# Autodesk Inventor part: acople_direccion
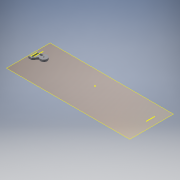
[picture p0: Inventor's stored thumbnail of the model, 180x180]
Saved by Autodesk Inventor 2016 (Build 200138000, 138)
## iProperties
Created: 2017-06
Part Number: acople_direccion
Material: Generic
Document SubType Name: Modeling
Designer: laboratorioesan
Density: 1 g/cm^3
Appearance: Default
Author: laboratorioesan
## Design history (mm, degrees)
workplane "Work Plane1"
sketch "Sketch1"
  geometry: L1 (-120, 104.183)-(-120, 85.683) reference; L2 (-120, 85.683)-(-180, 85.683) reference; L3 (-180, 85.683)-(-180, 104.183) reference; L4 (-180, 104.183)-(-120, 104.183) reference; L5 (370, 85.683)-(370, 104.183) reference; L6 (370, 104.183)-(430, 104.183) reference; L7 (430, 104.183)-(430, 85.683) reference; L8 (430, 85.683)-(370, 85.683) reference; L9 (180, 104.183)-(180, 85.683) reference; L10 (180, 85.683)-(120, 85.683) reference; L11 (120, 85.683)-(120, 104.183) reference; L12 (120, 104.183)-(180, 104.183) reference; L13 (-370, 104.183)-(-370, 85.683) reference; L14 (-370, 85.683)-(-430, 85.683) reference; L15 (-430, 85.683)-(-430, 104.183) reference; L16 (-430, 104.183)-(-370, 104.183) reference; L17 (448.5, -177.817)-(448.5, -117.817) reference; L18 (448.5, -117.817)-(467, -117.817) reference; L19 (467, -117.817)-(467, -177.817) reference; L20 (467, -177.817)-(448.5, -177.817) reference; L21 (-467, -177.817)-(-467, -117.817) reference; L22 (-467, -117.817)-(-448.5, -117.817) reference; L23 (-448.5, -117.817)-(-448.5, -177.817) reference; L24 (-448.5, -177.817)-(-467, -177.817) reference; L25 (400, 37.183)-(400, 55.683) reference; L26 (400, 55.683)-(460, 55.683) reference; L27 (460, 55.683)-(460, 37.183) reference; L28 (460, 37.183)-(400, 37.183) reference; L29 (190, 37.183)-(190, 55.683) reference; L30 (190, 55.683)-(250, 55.683) reference; L31 (250, 55.683)-(250, 37.183) reference; L32 (250, 37.183)-(190, 37.183) reference; L33 (-30, 37.183)-(-30, 55.683) reference; L34 (-30, 55.683)-(30, 55.683) reference; L35 (30, 55.683)-(30, 37.183) reference; L36 (30, 37.183)-(-30, 37.183) reference; L37 (-460, 37.183)-(-460, 55.683) reference; L38 (-460, 55.683)-(-400, 55.683) reference; L39 (-400, 55.683)-(-400, 37.183) reference; L40 (-400, 37.183)-(-460, 37.183) reference; L41 (-250, 37.183)-(-250, 55.683) reference; L42 (-250, 55.683)-(-190, 55.683) reference; L43 (-190, 55.683)-(-190, 37.183) reference; L44 (-190, 37.183)-(-250, 37.183) reference; L45 (-477.824, 115.072)-(-530, 37.183) reference; L46 (-530, 37.183)-(-530, -47.503) reference; L47 (-530, -47.503)-(-485.998, -191.117) reference; L48 (-428.63, -233.54)-(-370, -233.54) reference; L49 (-370, -233.54)-(-370, -52.817) reference; L50 (-310, 7.183)-(310, 7.183) reference; L51 (370, -52.817)-(370, -233.54) reference; L52 (370, -233.54)-(428.63, -233.54) reference; L53 (485.998, -191.117)-(530, -47.503) reference; L54 (530, -47.503)-(530, 37.183) reference; L55 (530, 37.183)-(477.824, 115.072) reference; L56 (427.975, 141.679)-(-427.975, 141.679) reference; L57 (-470, 37.183)-(-495, 55.683) reference; L58 (-460, 37.183)-(-470, 37.183) reference; L59 (-448.5, -92.817)-(-467, -92.817) reference; L60 (-505.617, 17.183)-(-560, 17.183); L61 (-560, 17.183)-(-560, -22.817); L62 (-558.781, 46.433)-(-560, 46.433); L63 (-560, 17.183)-(-560, -67.817); L64 (-560, -67.817)-(-530, -67.817)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; C1 r 5.25 at (-480, -2.817) reference; C2 r 5.25 at (480, -2.817) reference; A1 r 60 centre (-427.975, 81.679) between (-427.975, 141.679) and (-477.824, 115.072) reference; A2 r 60 centre (-428.63, -173.54) between (-485.998, -191.117) and (-428.63, -233.54) reference; A3 r 60 centre (-310, -52.817) between (-310, 7.183) and (-370, -52.817) reference; A4 r 60 centre (310, -52.817) between (370, -52.817) and (310, 7.183) reference; A5 r 60 centre (428.63, -173.54) between (428.63, -233.54) and (485.998, -191.117) reference; A6 r 60 centre (427.975, 81.679) between (477.824, 115.072) and (427.975, 141.679) reference; A7 r 32.5 centre (-480, -2.817) between (-499.816, -28.578) and (-505.617, 17.183); 3 further points
  constraints: 28 end point, 5 parallel, 4 horizontal, 4 perpendicular, 3 point on circle, 1 centre point, 1 coincident, 1 horizontal alignment, 1 midpoint, 1 point on line
  dimensions: "d0" = 65 diameter of A7; "d1" = 40 distance of L60.end L61.end; "d2" = 30 distance from line of L60.end L46; "d3" = 30 distance of L63.end L64.end; "d11" = 18.5 distance of L68.end L69.end; "d12" = 60 distance of L67.end L68.end; "d13" = 10 distance between parallel lines of L63 L68; "d14" = 12.5 distance between parallel lines of L64 L67; "d15" = 25 distance of L72.end L73.end; "d16" = 18.5 distance of L71.end L72.end; "d17" = 10 distance between parallel lines of L70 L72
extrude "Extrusion2" new body sketch "Sketch1" distance "d18" = 18.5; taper "d19" = 0 deg
sketch "Sketch2"
  geometry: L1 (-550, -55.317)-(-550, 4.683) reference; L2 (-530, 37.183)-(-530, -47.503) reference; L3 (530, -47.503)-(530, 37.183) reference; L4 (-530, 37.183)-(-530, -47.503) reference; 1 further point
  node "Reference6"
  node "Reference7"
  node "Reference8"
  node "Reference9"
body "Solid2"
node "Reference1"
node "Reference2"
node "Reference3"
node "Reference4"
node "Reference5"
